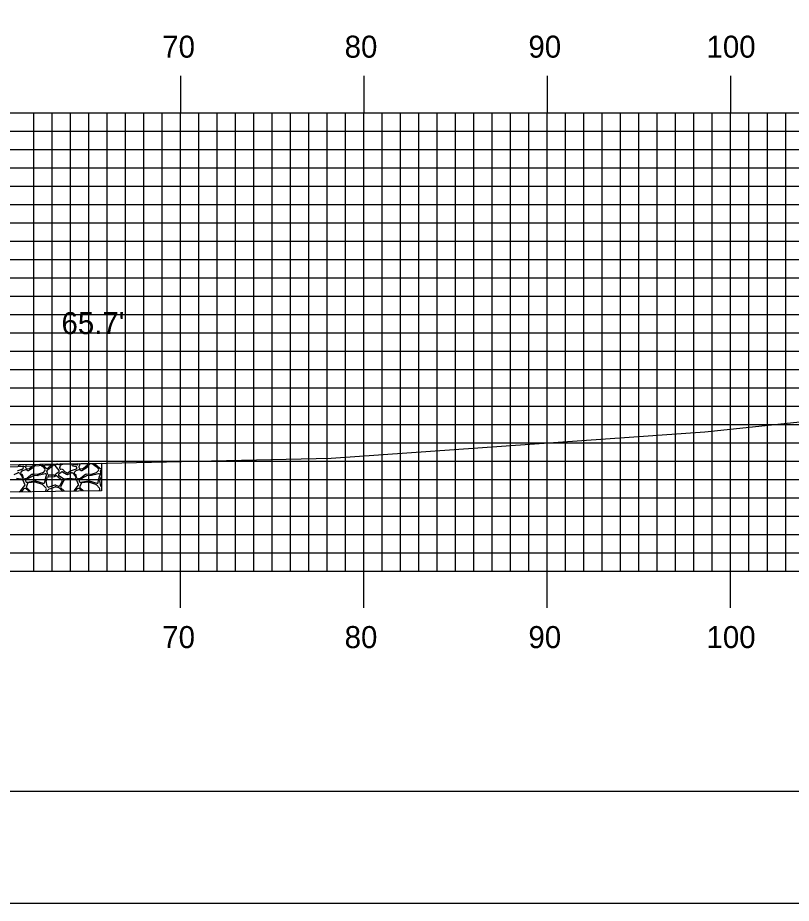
# Model space of a CAD drawing. Extents: x 1819244 to 1819587, y 442591 to 442811.
# Drawn here: x 1819470.79 to 1819512.97, y 442590.55 to 442638.84 of the extents above; entities that cross this region are included whole.
import ezdxf

# ---------------------------------------------------------------- set-up
doc = ezdxf.new("R2010")
doc.units = 0
for name, color, linetype in [('BORDER', 7, 'Continuous'), ('D_Roadway_SlopeLines', 7, 'Continuous'), ('D_Text_Standard', 7, 'Continuous'), ('H_V ANNOTATION', 7, 'Continuous'), ('MAJOR', 7, 'Continuous'), ('MINOR', 7, 'Continuous'), ('PLOT BOUNDARY', 7, 'Continuous'), ('S_Roadway_Centerline', 7, 'Continuous')]:
    doc.layers.add(name, color=color, linetype=linetype)

msp = doc.modelspace()

# ---------------------------------------------------------------- linework, layer by layer
at = {"layer": 'BORDER'}
msp.add_lwpolyline([(1819260.065, 442596.665), (1819580.065, 442596.665), (1819580.065, 442806.665), (1819260.065, 442806.665)], close=True, dxfattribs=at)
at = {"layer": 'D_Roadway_SlopeLines'}
for p, q in [((1819471.054, 442614.23), (1819470.787, 442614.136)), ((1819470.817, 442614.47), (1819470.819, 442614.459)), ((1819470.872, 442614.407), (1819471.042, 442614.372)), ((1819471.106, 442614.458), (1819470.921, 442614.464)), ((1819471.064, 442614.15), (1819471.226, 442614.213)), ((1819471.095, 442614.321), (1819471.097, 442614.31)), ((1819471.252, 442614.477), (1819471.204, 442614.352)), ((1819471.206, 442614.323), (1819471.246, 442614.255)), ((1819471.258, 442614.209), (1819471.33, 442614.157)), ((1819471.282, 442614.239), (1819471.438, 442614.267)), ((1819471.368, 442614.156), (1819471.653, 442614.33)), ((1819471.454, 442614.274), (1819471.673, 442614.451)), ((1819471.662, 442614.338), (1819471.775, 442614.486)), ((1819471.68, 442614.458), (1819471.697, 442614.484)), ((1819471.985, 442614.489), (1819472.147, 442614.365)), ((1819472.103, 442614.491), (1819472.338, 442614.279)), ((1819472.151, 442614.362), (1819472.267, 442614.237)), ((1819472.406, 442614.187), (1819472.721, 442614.437)), ((1819472.429, 442614.278), (1819472.634, 442614.458)), ((1819472.816, 442614.426), (1819472.891, 442614.335)), ((1819472.891, 442614.335), (1819473.037, 442614.158)), ((1819473.024, 442614.48), (1819472.927, 442614.505)), ((1819473.116, 442614.508), (1819473.073, 442614.485)), ((1819473.076, 442614.317), (1819473.121, 442614.421)), ((1819473.233, 442614.21), (1819473.131, 442614.221)), ((1819473.158, 442614.457), (1819473.287, 442614.511)), ((1819473.972, 442614.23), (1819473.706, 442614.136)), ((1819473.725, 442614.518), (1819473.738, 442614.459)), ((1819473.79, 442614.407), (1819473.961, 442614.372)), ((1819473.81, 442614.485), (1819473.795, 442614.519)), ((1819474.025, 442614.458), (1819473.84, 442614.464)), ((1819473.983, 442614.15), (1819474.145, 442614.213)), ((1819474.013, 442614.321), (1819474.016, 442614.31)), ((1819474.075, 442614.524), (1819474.058, 442614.48)), ((1819474.189, 442614.526), (1819474.123, 442614.352)), ((1819474.125, 442614.323), (1819474.165, 442614.255)), ((1819474.177, 442614.209), (1819474.249, 442614.157)), ((1819474.2, 442614.239), (1819474.357, 442614.267)), ((1819474.287, 442614.156), (1819474.571, 442614.33)), ((1819474.372, 442614.274), (1819474.591, 442614.451)), ((1819474.581, 442614.338), (1819474.731, 442614.535)), ((1819474.598, 442614.458), (1819474.649, 442614.534)), ((1819474.842, 442614.537), (1819475.066, 442614.365)), ((1819474.969, 442614.539), (1819475.257, 442614.279)), ((1819475.07, 442614.362), (1819475.186, 442614.237)), ((1819475.324, 442614.187), (1819475.351, 442614.208)), ((1819475.348, 442614.278), (1819475.351, 442614.281)), ((1819470.591, 442613.941), (1819470.802, 442614.025)), ((1819470.964, 442613.679), (1819470.714, 442613.716)), ((1819470.879, 442614.005), (1819471.016, 442613.845)), ((1819470.969, 442614.067), (1819471.054, 442614.144)), ((1819471.026, 442613.933), (1819470.983, 442613.955)), ((1819471.032, 442613.813), (1819471.041, 442613.759)), ((1819471.08, 442613.794), (1819471.061, 442613.886)), ((1819471.101, 442613.734), (1819471.083, 442613.785)), ((1819471.281, 442613.722), (1819471.185, 442613.692)), ((1819471.604, 442613.847), (1819471.25, 442613.66)), ((1819471.563, 442613.93), (1819471.302, 442613.732)), ((1819471.847, 442613.937), (1819471.606, 442613.944)), ((1819471.883, 442613.876), (1819471.63, 442613.855)), ((1819472.139, 442614.022), (1819471.868, 442613.94)), ((1819472.277, 442613.972), (1819471.893, 442613.878)), ((1819472.266, 442614.143), (1819472.168, 442614.04)), ((1819472.261, 442613.512), (1819472.313, 442613.772)), ((1819472.316, 442613.784), (1819472.356, 442613.88)), ((1819472.342, 442613.625), (1819472.406, 442613.77)), ((1819472.424, 442613.941), (1819472.382, 442614.117)), ((1819472.466, 442613.81), (1819472.768, 442613.823)), ((1819472.769, 442613.889), (1819472.491, 442613.888)), ((1819472.788, 442613.827), (1819472.871, 442613.856)), ((1819472.891, 442613.961), (1819472.81, 442613.902)), ((1819473.024, 442614.059), (1819472.891, 442613.961)), ((1819472.936, 442613.846), (1819473.191, 442613.649)), ((1819473.03, 442613.964), (1819473.156, 442614.066)), ((1819473.276, 442613.688), (1819473.034, 442613.855)), ((1819473.233, 442614.072), (1819473.451, 442613.946)), ((1819473.294, 442614.146), (1819473.294, 442614.151)), ((1819473.613, 442613.716), (1819473.325, 442613.676)), ((1819473.463, 442614.023), (1819473.33, 442614.094)), ((1819473.51, 442613.941), (1819473.721, 442614.025)), ((1819473.691, 442614.129), (1819473.532, 442614.026)), ((1819473.883, 442613.679), (1819473.632, 442613.716)), ((1819473.798, 442614.005), (1819473.935, 442613.845)), ((1819473.887, 442614.067), (1819473.972, 442614.144)), ((1819473.945, 442613.933), (1819473.902, 442613.955)), ((1819473.95, 442613.813), (1819473.96, 442613.759)), ((1819473.999, 442613.794), (1819473.98, 442613.886)), ((1819474.019, 442613.734), (1819474.001, 442613.785)), ((1819474.2, 442613.722), (1819474.104, 442613.692)), ((1819474.523, 442613.847), (1819474.169, 442613.66)), ((1819474.482, 442613.93), (1819474.22, 442613.732)), ((1819474.765, 442613.937), (1819474.525, 442613.944)), ((1819474.801, 442613.876), (1819474.549, 442613.855)), ((1819475.057, 442614.022), (1819474.787, 442613.94)), ((1819475.195, 442613.972), (1819474.812, 442613.878)), ((1819475.185, 442614.143), (1819475.087, 442614.04)), ((1819475.18, 442613.512), (1819475.231, 442613.772)), ((1819475.235, 442613.784), (1819475.275, 442613.88)), ((1819475.261, 442613.625), (1819475.325, 442613.77)), ((1819475.343, 442613.941), (1819475.3, 442614.117)), ((1819471.055, 442613.617), (1819470.771, 442613.649)), ((1819470.965, 442613.06), (1819471.171, 442613.325)), ((1819471.18, 442613.391), (1819471.111, 442613.573)), ((1819471.216, 442613.582), (1819471.223, 442613.559)), ((1819471.319, 442613.439), (1819471.258, 442613.27)), ((1819471.301, 442613.51), (1819471.729, 442613.587)), ((1819471.715, 442613.522), (1819471.375, 442613.483)), ((1819472.136, 442613.383), (1819471.745, 442613.519)), ((1819471.76, 442613.585), (1819472.174, 442613.46)), ((1819472.332, 442613.189), (1819472.163, 442613.366)), ((1819472.4, 442613.298), (1819472.338, 442613.583)), ((1819472.82, 442613.342), (1819472.486, 442613.247)), ((1819472.645, 442613.183), (1819472.836, 442613.251)), ((1819472.891, 442613.333), (1819472.857, 442613.342)), ((1819472.871, 442613.254), (1819472.891, 442613.251)), ((1819472.998, 442613.302), (1819472.891, 442613.333)), ((1819472.891, 442613.251), (1819473.007, 442613.23)), ((1819473.208, 442613.56), (1819473.076, 442613.333)), ((1819473.281, 442613.579), (1819473.132, 442613.286)), ((1819473.676, 442613.649), (1819473.336, 442613.616)), ((1819473.974, 442613.617), (1819473.69, 442613.649)), ((1819473.884, 442613.06), (1819474.089, 442613.325)), ((1819474.099, 442613.391), (1819474.03, 442613.573)), ((1819474.135, 442613.582), (1819474.142, 442613.559)), ((1819474.238, 442613.439), (1819474.177, 442613.27)), ((1819474.219, 442613.51), (1819474.647, 442613.587)), ((1819474.634, 442613.522), (1819474.294, 442613.483)), ((1819475.055, 442613.383), (1819474.664, 442613.519)), ((1819474.679, 442613.585), (1819475.093, 442613.46)), ((1819475.251, 442613.189), (1819475.082, 442613.366)), ((1819475.319, 442613.298), (1819475.257, 442613.583)), ((1819470.867, 442612.979), (1819470.943, 442613.039)), ((1819470.943, 442613.039), (1819470.954, 442613.048)), ((1819471.024, 442613.039), (1819470.984, 442612.981)), ((1819471.079, 442613.12), (1819471.024, 442613.039)), ((1819471.181, 442613.167), (1819471.115, 442613.147)), ((1819471.376, 442613.039), (1819471.245, 442613.153)), ((1819471.277, 442613.196), (1819471.452, 442613.039)), ((1819471.435, 442612.987), (1819471.376, 442613.039)), ((1819471.452, 442613.039), (1819471.509, 442612.988)), ((1819472.296, 442613), (1819472.312, 442613.039)), ((1819472.312, 442613.039), (1819472.345, 442613.115)), ((1819472.382, 442613.016), (1819472.4, 442613.039)), ((1819472.4, 442613.039), (1819472.462, 442613.119)), ((1819472.498, 442613.142), (1819472.64, 442613.181)), ((1819473.042, 442613.213), (1819473.219, 442613.049)), ((1819473.145, 442613.207), (1819473.313, 442613.039)), ((1819473.313, 442613.039), (1819473.336, 442613.015)), ((1819473.841, 442613.023), (1819473.861, 442613.039)), ((1819473.861, 442613.039), (1819473.873, 442613.048)), ((1819473.942, 442613.039), (1819473.932, 442613.024)), ((1819473.998, 442613.12), (1819473.942, 442613.039)), ((1819474.099, 442613.167), (1819474.034, 442613.147)), ((1819474.294, 442613.039), (1819474.164, 442613.153)), ((1819474.195, 442613.196), (1819474.371, 442613.039)), ((1819474.305, 442613.03), (1819474.294, 442613.039)), ((1819474.371, 442613.039), (1819474.38, 442613.031)), ((1819475.233, 442613.043), (1819475.264, 442613.115)), ((1819475.323, 442613.045), (1819475.351, 442613.081))]:
    msp.add_line(p, q, dxfattribs=at)
msp.add_lwpolyline([(1819461.851, 442614.332), (1819475.351, 442614.545), (1819475.351, 442613.045), (1819460.253, 442612.822)], dxfattribs=at)
for centre, major_axis, start_param, end_param in [((1819470.886, 442614.474), (0, -0.0683), 4.928939, 6.08014), ((1819470.923, 442614.499), (0, -0.0342), 5.644924, 6.25041), ((1819471.028, 442614.305), (0, 0.0683), 4.941621, 6.08014), ((1819471.031, 442614.294), (0, 0.0683), 3.480291, 4.941621), ((1819471.107, 442614.493), (0, -0.0342), 6.25041, 7.316921), ((1819471.236, 442614.34), (0, 0.0342), 1.204402, 2.105751), ((1819471.238, 442614.181), (0, 0.0342), 5.662936, 6.653091), ((1819471.276, 442614.273), (0, -0.0342), 5.247344, 6.461278), ((1819471.432, 442614.301), (0, -0.0342), 0.178093, 0.676737), ((1819471.635, 442614.359), (0, -0.0342), 0.547562, 0.91795), ((1819471.651, 442614.477), (0, -0.0342), 0.676737, 0.982794), ((1819472.126, 442614.338), (0, 0.0342), 5.459199, 5.630339), ((1819472.217, 442614.19), (0, 0.0683), 3.950796, 5.459199), ((1819472.384, 442614.329), (0, -0.0683), 5.54801, 7.003068), ((1819472.448, 442614.133), (0, -0.0683), 3.811328, 4.949439), ((1819472.589, 442614.51), (0, -0.0683), 0.719883, 1.435332), ((1819472.763, 442614.383), (0, 0.0683), 5.401291, 6.952921), ((1819473.041, 442614.546), (0, -0.0683), 6.025862, 6.773143), ((1819473.138, 442614.289), (0, -0.0683), 4.299059, 6.17752), ((1819473.184, 442614.394), (0, 0.0683), 0.394791, 1.157466), ((1819473.226, 442614.143), (0, 0.0683), 4.831818, 6.17752), ((1819473.804, 442614.474), (0, -0.0683), 4.928939, 6.08014), ((1819473.841, 442614.499), (0, -0.0342), 5.126896, 6.25041), ((1819473.947, 442614.305), (0, 0.0683), 4.941621, 6.08014), ((1819473.95, 442614.294), (0, 0.0683), 3.480291, 4.941621), ((1819474.026, 442614.493), (0, -0.0342), 6.25041, 7.473475), ((1819474.154, 442614.34), (0, 0.0342), 1.204402, 2.105751), ((1819474.157, 442614.181), (0, 0.0342), 5.662936, 6.653091), ((1819474.194, 442614.273), (0, -0.0342), 5.247344, 6.461278), ((1819474.351, 442614.301), (0, -0.0342), 0.178093, 0.676737), ((1819474.553, 442614.359), (0, -0.0342), 0.547562, 0.91795), ((1819474.57, 442614.477), (0, -0.0342), 0.676737, 0.982794), ((1819475.045, 442614.338), (0, 0.0342), 5.459199, 5.630339), ((1819475.135, 442614.19), (0, 0.0683), 3.950796, 5.459199), ((1819475.303, 442614.329), (0, -0.0683), 5.54801, 7.003068), ((1819475.367, 442614.133), (0, -0.0683), 3.811328, 4.949439), ((1819470.81, 442614.071), (0, 0.0683), 0.338698, 0.570383), ((1819470.827, 442613.961), (0, 0.0683), 5.421015, 6.659146), ((1819471.014, 442614.016), (0, -0.0683), 3.878249, 5.800672), ((1819470.974, 442613.747), (0, 0.0683), 2.993743, 4.892242), ((1819470.964, 442613.801), (0, 0.0683), 4.892242, 5.421015), ((1819470.994, 442613.872), (0, 0.0683), 4.915434, 5.800672), ((1819471.077, 442614.119), (0, 0.0342), 0.369906, 0.736656), ((1819471.147, 442613.808), (0, -0.0683), 4.915434, 5.053368), ((1819471.165, 442613.757), (0, -0.0683), 5.053368, 6.584804), ((1819471.261, 442613.787), (0, -0.0683), 0.301619, 0.645576), ((1819471.35, 442614.185), (0, -0.0342), 5.662936, 6.830748), ((1819471.605, 442613.875), (0, 0.0683), 6.255795, 6.928761), ((1819471.636, 442613.787), (0, 0.0683), 0.083141, 0.485227), ((1819471.849, 442614.005), (0, -0.0683), 6.255795, 6.578122), ((1819471.877, 442613.944), (0, -0.0683), 0.083141, 0.241894), ((1819472.119, 442614.087), (0, -0.0683), 0.294937, 0.809203), ((1819472.293, 442613.906), (0, -0.0683), 1.177705, 3.383486), ((1819472.379, 442613.758), (0, 0.0683), 1.177705, 1.37369), ((1819472.469, 442613.742), (0, 0.0683), 0.042528, 1.152572), ((1819472.491, 442613.957), (0, -0.0683), 4.949439, 6.284735), ((1819472.765, 442613.891), (0, -0.0683), 0.042528, 0.339293), ((1819472.769, 442613.957), (0, -0.0683), 0.001549, 0.632145), ((1819472.894, 442613.792), (0, 0.0683), 0.046753, 0.339293), ((1819472.894, 442613.792), (0, 0.0683), 5.625297, 6.329939), ((1819473.073, 442613.911), (0, -0.0683), 3.820255, 5.679955), ((1819472.984, 442614.114), (0, 0.0683), 3.773738, 5.401291), ((1819473.199, 442614.013), (0, 0.0683), 5.75839, 6.961848), ((1819473.362, 442614.154), (0, -0.0683), 4.831818, 5.797153), ((1819473.485, 442614.005), (0, -0.0683), 5.75839, 6.659146), ((1819473.495, 442614.084), (0, -0.0683), 5.797153, 6.853569), ((1819473.622, 442613.649), (0, 0.0683), 6.135336, 6.421825), ((1819473.728, 442614.071), (0, 0.0683), 0.338698, 0.570383), ((1819473.746, 442613.961), (0, 0.0683), 5.421015, 6.659146), ((1819473.933, 442614.016), (0, -0.0683), 3.878249, 5.800672), ((1819473.893, 442613.747), (0, 0.0683), 2.993743, 4.892242), ((1819473.883, 442613.801), (0, 0.0683), 4.892242, 5.421015), ((1819473.913, 442613.872), (0, 0.0683), 4.915434, 5.800672), ((1819473.995, 442614.119), (0, 0.0342), 0.369906, 0.736656), ((1819474.066, 442613.808), (0, -0.0683), 4.915434, 5.053368), ((1819474.084, 442613.757), (0, -0.0683), 5.053368, 6.584804), ((1819474.179, 442613.787), (0, -0.0683), 0.301619, 0.645576), ((1819474.269, 442614.185), (0, -0.0342), 5.662936, 6.830748), ((1819474.523, 442613.875), (0, 0.0683), 6.255795, 6.928761), ((1819474.555, 442613.787), (0, 0.0683), 0.083141, 0.485227), ((1819474.767, 442614.005), (0, -0.0683), 6.255795, 6.578122), ((1819474.796, 442613.944), (0, -0.0683), 0.083141, 0.241894), ((1819475.037, 442614.087), (0, -0.0683), 0.294937, 0.809203), ((1819475.212, 442613.906), (0, -0.0683), 1.177705, 3.383486), ((1819475.298, 442613.758), (0, 0.0683), 1.177705, 1.37369), ((1819475.387, 442613.742), (0, 0.0683), 0.555016, 1.152572), ((1819475.409, 442613.957), (0, -0.0683), 4.949439, 5.266934), ((1819471.047, 442613.549), (0, 0.0683), 5.07759, 6.170034), ((1819471.117, 442613.367), (0, -0.0683), 0.911486, 1.935998), ((1819471.282, 442613.6), (0, 0.0683), 0.485227, 1.841743), ((1819471.289, 442613.577), (0, -0.0683), 4.983336, 6.460411), ((1819471.322, 442613.247), (0, 0.0683), 1.223118, 2.412764), ((1819471.383, 442613.415), (0, 0.0683), 0.113874, 1.223118), ((1819471.723, 442613.454), (0, 0.0683), 5.950458, 6.397059), ((1819471.741, 442613.519), (0, 0.0683), 5.991139, 6.460411), ((1819472.114, 442613.319), (0, 0.0683), 5.472885, 5.950458), ((1819472.194, 442613.526), (0, -0.0683), 5.991139, 7.656876), ((1819472.404, 442613.597), (0, -0.0683), 4.294165, 4.928939), ((1819472.467, 442613.313), (0, -0.0683), 4.928939, 6.561485), ((1819472.838, 442613.277), (0, 0.0683), 6.004886, 6.561485), ((1819472.859, 442613.187), (0, 0.0683), 6.110994, 6.626209), ((1819473.017, 442613.368), (0, -0.0683), 6.004886, 7.327354), ((1819472.995, 442613.163), (0, 0.0683), 5.534807, 6.110994), ((1819473.193, 442613.255), (0, 0.0683), 1.099019, 2.356194), ((1819473.149, 442613.595), (0, 0.0683), 4.185762, 5.625297), ((1819473.315, 442613.744), (0, -0.0683), 5.679955, 6.421825), ((1819473.342, 442613.548), (0, 0.0683), 0.097727, 1.099019), ((1819473.682, 442613.581), (0, 0.0683), 6.170034, 6.380912), ((1819473.966, 442613.549), (0, 0.0683), 5.07759, 6.170034), ((1819474.035, 442613.367), (0, -0.0683), 0.911486, 1.935998), ((1819474.201, 442613.6), (0, 0.0683), 0.485227, 1.841743), ((1819474.207, 442613.577), (0, -0.0683), 4.983336, 6.460411), ((1819474.241, 442613.247), (0, 0.0683), 1.223118, 2.412764), ((1819474.302, 442613.415), (0, 0.0683), 0.113874, 1.223118), ((1819474.641, 442613.454), (0, 0.0683), 5.950458, 6.397059), ((1819474.659, 442613.519), (0, 0.0683), 5.991139, 6.460411), ((1819475.033, 442613.319), (0, 0.0683), 5.472885, 5.950458), ((1819475.113, 442613.526), (0, -0.0683), 5.991139, 7.656876), ((1819475.323, 442613.597), (0, -0.0683), 4.294165, 4.928939), ((1819475.386, 442613.313), (0, -0.0683), 4.928939, 5.756642), ((1819470.911, 442613.102), (0, -0.0683), 0.674741, 0.911486), ((1819471.135, 442613.082), (0, 0.0683), 0.294235, 0.97362), ((1819471.2, 442613.102), (0, 0.0683), 5.565745, 6.57742), ((1819472.282, 442613.142), (0, -0.0683), 1.163165, 2.331293), ((1819472.436, 442612.974), (0, -0.0683), 4.048343, 4.302961), ((1819472.516, 442613.076), (0, 0.0683), 0.266252, 0.90675), ((1819472.622, 442613.247), (0, -0.0683), 0.266252, 0.343024), ((1819473.172, 442612.998), (0, 0.0683), 5.35086, 5.534807), ((1819473.172, 442612.998), (0, 0.0683), 4.940521, 5.35086), ((1819473.83, 442613.102), (0, -0.0683), 0.674741, 0.911486), ((1819474.054, 442613.082), (0, 0.0683), 0.294235, 0.97362), ((1819474.119, 442613.102), (0, 0.0683), 5.565745, 6.57742), ((1819475.201, 442613.142), (0, -0.0683), 1.163165, 2.331293)]:
    msp.add_ellipse(centre, major_axis=major_axis, ratio=0.99895, start_param=start_param, end_param=end_param, dxfattribs=at)
at = {"layer": 'MAJOR'}
for p, q in [((1819479.665, 442635.669), (1819479.665, 442633.665)), ((1819489.665, 442635.669), (1819489.665, 442633.665)), ((1819499.665, 442635.669), (1819499.665, 442633.665)), ((1819509.665, 442635.669), (1819509.665, 442633.665)), ((1819269.665, 442633.665), (1819549.665, 442633.665)), ((1819269.665, 442633.665), (1819549.665, 442633.665)), ((1819479.665, 442608.665), (1819479.665, 442633.665)), ((1819489.665, 442608.665), (1819489.665, 442633.665)), ((1819499.665, 442608.665), (1819499.665, 442633.665)), ((1819509.665, 442608.665), (1819509.665, 442633.665)), ((1819269.665, 442628.665), (1819549.665, 442628.665)), ((1819269.665, 442623.665), (1819549.665, 442623.665)), ((1819269.665, 442618.665), (1819549.665, 442618.665)), ((1819269.665, 442613.665), (1819549.665, 442613.665)), ((1819269.665, 442608.665), (1819549.665, 442608.665)), ((1819269.665, 442608.665), (1819549.665, 442608.665)), ((1819479.665, 442606.661), (1819479.665, 442608.665)), ((1819489.665, 442606.661), (1819489.665, 442608.665)), ((1819499.665, 442606.661), (1819499.665, 442608.665)), ((1819509.665, 442606.661), (1819509.665, 442608.665))]:
    msp.add_line(p, q, dxfattribs=at)
at = {"layer": 'MINOR'}
for p, q in [((1819471.665, 442608.665), (1819471.665, 442633.665)), ((1819472.665, 442608.665), (1819472.665, 442633.665)), ((1819473.665, 442608.665), (1819473.665, 442633.665)), ((1819474.665, 442608.665), (1819474.665, 442633.665)), ((1819475.665, 442608.665), (1819475.665, 442633.665)), ((1819476.665, 442608.665), (1819476.665, 442633.665)), ((1819477.665, 442608.665), (1819477.665, 442633.665)), ((1819478.665, 442608.665), (1819478.665, 442633.665)), ((1819480.665, 442608.665), (1819480.665, 442633.665)), ((1819481.665, 442608.665), (1819481.665, 442633.665)), ((1819482.665, 442608.665), (1819482.665, 442633.665)), ((1819483.665, 442608.665), (1819483.665, 442633.665)), ((1819484.665, 442608.665), (1819484.665, 442633.665)), ((1819485.665, 442608.665), (1819485.665, 442633.665)), ((1819486.665, 442608.665), (1819486.665, 442633.665)), ((1819487.665, 442608.665), (1819487.665, 442633.665)), ((1819488.665, 442608.665), (1819488.665, 442633.665)), ((1819490.665, 442608.665), (1819490.665, 442633.665)), ((1819491.665, 442608.665), (1819491.665, 442633.665)), ((1819492.665, 442608.665), (1819492.665, 442633.665)), ((1819493.665, 442608.665), (1819493.665, 442633.665)), ((1819494.665, 442608.665), (1819494.665, 442633.665)), ((1819495.665, 442608.665), (1819495.665, 442633.665)), ((1819496.665, 442608.665), (1819496.665, 442633.665)), ((1819497.665, 442608.665), (1819497.665, 442633.665)), ((1819498.665, 442608.665), (1819498.665, 442633.665)), ((1819500.665, 442608.665), (1819500.665, 442633.665)), ((1819501.665, 442608.665), (1819501.665, 442633.665)), ((1819502.665, 442608.665), (1819502.665, 442633.665)), ((1819503.665, 442608.665), (1819503.665, 442633.665)), ((1819504.665, 442608.665), (1819504.665, 442633.665)), ((1819505.665, 442608.665), (1819505.665, 442633.665)), ((1819506.665, 442608.665), (1819506.665, 442633.665)), ((1819507.665, 442608.665), (1819507.665, 442633.665)), ((1819508.665, 442608.665), (1819508.665, 442633.665)), ((1819510.665, 442608.665), (1819510.665, 442633.665)), ((1819511.665, 442608.665), (1819511.665, 442633.665)), ((1819512.665, 442608.665), (1819512.665, 442633.665)), ((1819269.665, 442632.665), (1819549.665, 442632.665)), ((1819269.665, 442631.665), (1819549.665, 442631.665)), ((1819269.665, 442630.665), (1819549.665, 442630.665)), ((1819269.665, 442629.665), (1819549.665, 442629.665)), ((1819269.665, 442627.665), (1819549.665, 442627.665)), ((1819269.665, 442626.665), (1819549.665, 442626.665)), ((1819269.665, 442625.665), (1819549.665, 442625.665)), ((1819269.665, 442624.665), (1819549.665, 442624.665)), ((1819269.665, 442622.665), (1819549.665, 442622.665)), ((1819269.665, 442621.665), (1819549.665, 442621.665)), ((1819269.665, 442620.665), (1819549.665, 442620.665)), ((1819269.665, 442619.665), (1819549.665, 442619.665)), ((1819269.665, 442617.665), (1819549.665, 442617.665)), ((1819269.665, 442616.665), (1819549.665, 442616.665)), ((1819269.665, 442615.665), (1819549.665, 442615.665)), ((1819269.665, 442614.665), (1819549.665, 442614.665)), ((1819269.665, 442612.665), (1819549.665, 442612.665)), ((1819269.665, 442611.665), (1819549.665, 442611.665)), ((1819269.665, 442610.665), (1819549.665, 442610.665)), ((1819269.665, 442609.665), (1819549.665, 442609.665))]:
    msp.add_line(p, q, dxfattribs=at)
at = {"layer": 'PLOT BOUNDARY'}
msp.add_lwpolyline([(1819243.878, 442590.547), (1819583.878, 442590.547), (1819583.878, 442810.547), (1819243.878, 442810.547)], close=True, dxfattribs=at)
at = {"layer": 'S_Roadway_Centerline'}
msp.add_lwpolyline([(1819469.488, 442614.315), (1819471.654, 442614.398), (1819473.184, 442614.498), (1819487.884, 442614.82), (1819508.262, 442616.254), (1819528.3, 442618.36), (1819549.665, 442620.426)], dxfattribs=at)

# ---------------------------------------------------------------- texts
at = {"layer": 'D_Text_Standard'}
msp.add_text("65.7'", height=1.2, dxfattribs=at).set_placement((1819473.174, 442621.59))
at = {"layer": 'H_V ANNOTATION'}
for s, p in [('70', (1819478.669, 442636.665)), ('80', (1819488.615, 442636.665)), ('90', (1819498.637, 442636.665)), ('100', (1819508.348, 442636.665)), ('70', (1819478.669, 442604.465)), ('80', (1819488.615, 442604.465)), ('90', (1819498.637, 442604.465)), ('100', (1819508.348, 442604.465))]:
    msp.add_text(s, height=1.2, dxfattribs=at).set_placement(p)

doc.saveas('drawing.dxf')
